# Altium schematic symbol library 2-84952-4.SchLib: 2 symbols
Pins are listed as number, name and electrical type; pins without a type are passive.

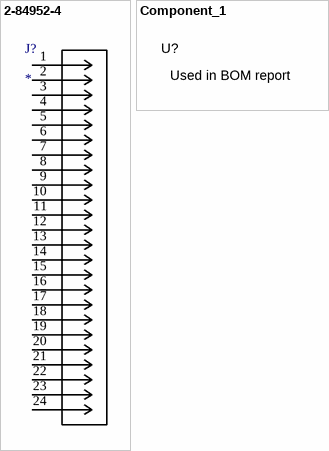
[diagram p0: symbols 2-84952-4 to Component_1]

## 2-84952-4
designator J?
Imported; Manufacturer_Part_Number: 2-84952-4; Manufacturer_Name: Tyco Electronics Amp; Vendor: Tyco Electronics; Supersection: Connectors; Section: General Purpose
footprint CON24_SMT-RA_FCC
pins: 1, 2, 3, 4, 5, 6, 7, 8, 9, 10, 11, 12, 13, 14, 15, 16, 17, 18, 19, 20, 21, 22, 23, 24

## Component_1
designator U?, comment Used in BOM report
SymbolVersion: use current date i.e. 2008-05-20; SymbolCreator: Use a-id; CompType: Used in some BOM reports.  Useful for finding later.; U/M: EA, IN, or GM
